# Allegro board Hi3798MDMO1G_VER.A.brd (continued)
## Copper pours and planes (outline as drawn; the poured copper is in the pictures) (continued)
$14N770 on BOTTOM (solid shape): 16.22,62.2 16.22,56.82 16.09,56.69 15.07,56.69 14.9,56.87 14.9,58.67 15.97,58.67 15.97,59.05 15.59,59.05 15.59,58.67 14.9,58.67 14.9,59.31 15.97,59.31 15.97,59.69 15.59,59.69 15.59,59.31 14.9,59.31 14.9,60.13 14.69,60.33 14.69,62.15 14.9,62.35 16.06,62.35
$16N1165 on BOTTOM (solid shape): 30.74,72 30.74,70.42 30.62,70.29 21.67,70.29 21.57,70.39 21.57,71.06 21.67,71.16 28.79,71.16 28.94,71.31 28.94,72 29.12,72.17 30.56,72.17

Small or netless copper shapes (teardrops, artwork), in the pictures only: 3 on TOP, 5 on BOTTOM

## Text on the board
BOTTOM: HI3798MDMO1G VER.A ARTWORK BOTTOM
Package Geometry/Pastemask Bottom: HI3798MDMO1G VER.A PASTEMASK BOTTOM
Ref Des/Silkscreen Bottom: C | HI3798MDMO1G VER.A SILKCREEN BOTTOM
User.Comments: HI3798MDMO1G VER.A SOLDERMASK TOP | HI3798MDMO1G VER.A SOLDERMASK BOTTOM
TOP: HI3798MDMO1G VER.A ARTWORK TOP
Package Geometry/Pastemask Top: HI3798MDMO1G VER.A PASTEMASK TOP
Ref Des/Silkscreen Top: B | A | HI3798MDMO1G VER.A SILKCREEN TOP | HI3798MDMO1G VER.A
GND02: HI3798MDMO1G VER.A ARTWORK LAYER02
POWER03: HI3798MDMO1G VER.A ARTWORK LAYER03
DIMENSION: Notes3: | For this PN,Soldermask should be covered at all required location and | no red solder(copper color) is allowed at BGA area | 8XR2[78]
User.10: FIGURE | SIZE | 8.0 | 10.0 | 20.0 | 32.0 | 36.0 | 38.0 | 40.0 | 52.0 | 90.0 | 142.0 | 43.0 | 80.0 | 135.0 | 52.0x24.0 | 60.0x32.0 | 82.0x36.0 | 96.0x26.0 | 96.0x30.0 | 105.0x36.0 | 116.0x30.0 | DRILL CHART: TOP to BOTTOM | ALL UNITS ARE IN MILS | PLATED | NON-PLATED | QTY | 246 | 1064 | 4 | 3 | 13 | 22 | 2 | 32 | 5 | 1
